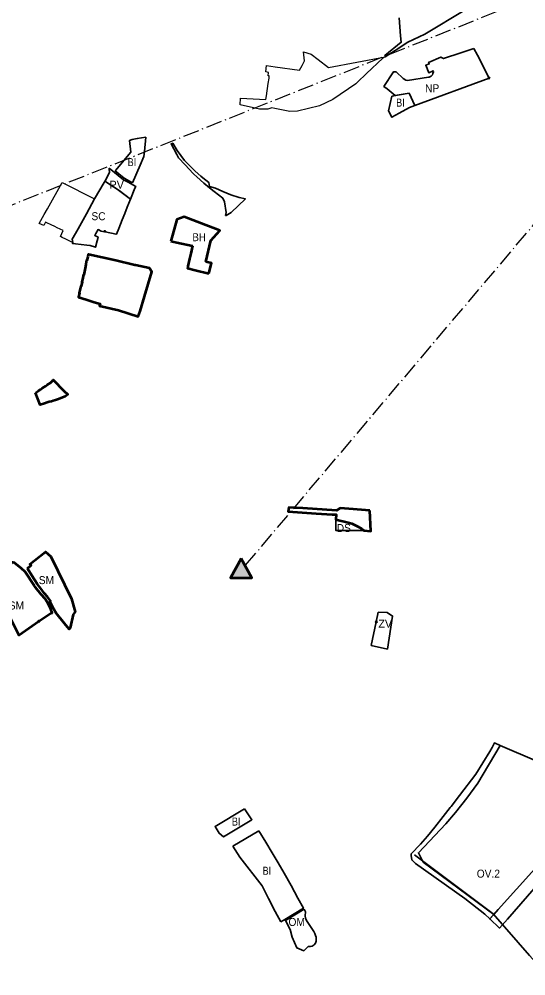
# Model space of a CAD drawing. Extents: x -650276 to -642489, y -1074311 to -1066658.
# Drawn here: x -646929 to -646170, y -1071706 to -1070271 of the extents above; entities that cross this region are included whole.
import ezdxf

# ---------------------------------------------------------------- set-up
doc = ezdxf.new("R2010")
doc.units = 0
doc.header["$LTSCALE"] = 4.8
doc.header["$PDMODE"] = 32
doc.header["$PDSIZE"] = 2.4
doc.linetypes.add('DOT_DASHED', pattern=[7.7, 5, -1.2, 0.3, -1.2])
for name, color, linetype, lineweight in [('1', 7, 'Continuous', 35), ('11', 7, 'Continuous', 35), ('12', 7, 'Continuous', 35), ('15', 7, 'Continuous', 35), ('17', 7, 'Continuous', 35), ('18', 7, 'Continuous', 35), ('2', 7, 'Continuous', 35), ('24', 7, 'Continuous', 35), ('40', 7, 'Continuous', 35), ('48', 7, 'Continuous', 35), ('54', 7, 'Continuous', 35), ('55', 7, 'Continuous', 53), ('60', 7, 'Continuous', 53), ('61', 7, 'Continuous', 25)]:
    doc.layers.add(name, color=color, linetype=linetype, lineweight=lineweight)
doc.layers.add('62', color=7, linetype='Continuous')
doc.layers.add('63', color=7, linetype='Continuous')

msp = doc.modelspace()

# ---------------------------------------------------------------- hatches: boundary and pattern name
at = {"layer": '55'}
msp.add_hatch(color=256, dxfattribs=at).paths.add_polyline_path([(-646596.857, -1071079.969), (-646612.808, -1071108.615), (-646580.424, -1071108.615)])

# ---------------------------------------------------------------- linework, layer by layer
at = {"layer": '1'}
msp.add_line((-646665.42, -1070647.54), (-646645.03, -1070652.34), dxfattribs=at)
for points in [[(-646655.95, -1070577.64), (-646682.29, -1070567.36), (-646692.98, -1070571.45), (-646701.87, -1070603.92)], [(-646649.71, -1070634.85), (-646642.32, -1070603.3), (-646628.69, -1070588.27), (-646655.95, -1070577.64)], [(-646701.87, -1070603.92), (-646693.18, -1070605.83), (-646669.59, -1070611.01), (-646672.13, -1070622.41), (-646673.91, -1070630.38), (-646676.414, -1070641.58)], [(-646676.414, -1070641.58), (-646676.81, -1070643.36), (-646677.13, -1070644.78), (-646665.42, -1070647.54)], [(-646645.03, -1070652.34), (-646641.09, -1070636.89), (-646649.71, -1070634.85)]]:
    msp.add_lwpolyline(points, dxfattribs=at)
at = {"layer": '11'}
msp.add_lwpolyline([(-646066.165, -1071422.155), (-646153.5, -1071383.85), (-646208.577, -1071360.044), (-646241.68, -1071416.887), (-646258.487, -1071439.265), (-646275.615, -1071460.886), (-646289.976, -1071477.514), (-646330.914, -1071521.11), (-646324, -1071535), (-646217.978, -1071613.552), (-646211.407, -1071606.247), (-646156.471, -1071545.166), (-646094.063, -1071471.007)], close=True, dxfattribs=at)
at = {"layer": '12'}
msp.add_lwpolyline([(-646502.39, -1071605.72), (-646530.27, -1071622.79), (-646522.99, -1071636.22), (-646520.32, -1071647.59), (-646513.43, -1071663.64), (-646502.53, -1071667.82), (-646496.06, -1071661.5), (-646492.89, -1071661.75), (-646490.07, -1071660.88), (-646487.36, -1071659.1), (-646485.29, -1071656.53), (-646484.15, -1071653.38), (-646483.97, -1071650.63), (-646484.38, -1071647.41), (-646485.2, -1071644.85), (-646486.31, -1071641.97), (-646487.56, -1071639.23), (-646497.83, -1071624.02), (-646499.829, -1071620.704), (-646500.289, -1071619.291), (-646500.83, -1071615.62), (-646500.34, -1071609.66)], close=True, dxfattribs=at)
at = {"layer": '15'}
for points in [[(-646623.95, -1070529.36), (-646634.85, -1070524.43), (-646644.2, -1070522.08), (-646645.31, -1070515.85), (-646654, -1070509), (-646656.83, -1070506.66), (-646665.457, -1070499.019), (-646667.42, -1070497.28), (-646681.6, -1070482.89), (-646692.74, -1070468.28), (-646699.26, -1070457.2), (-646701.65, -1070457.93), (-646693.119, -1070474.009), (-646690.316, -1070479.212), (-646680.44, -1070489.669), (-646668.361, -1070502.459), (-646667.369, -1070503.36), (-646662.895, -1070507.428), (-646652.352, -1070517.013), (-646643.895, -1070524.284), (-646637.158, -1070529.564), (-646624.211, -1070539.711), (-646621.729, -1070545.248), (-646619.34, -1070560.95), (-646619.99, -1070565.54), (-646619.15, -1070565.53), (-646611.41, -1070560.96), (-646590.2, -1070540.66), (-646599.81, -1070538.51), (-646611.88, -1070534.82)], [(-646275.615, -1071460.886), (-646258.487, -1071439.265), (-646241.68, -1071416.887), (-646208.577, -1071360.044), (-646217.049, -1071356.382), (-646220.61, -1071363.16), (-646223.77, -1071369.24), (-646245.1, -1071403.04), (-646269.2, -1071435.22), (-646281.99, -1071451.4), (-646283.52, -1071453.34), (-646293.87, -1071466.43), (-646306.14, -1071482.86), (-646317.52, -1071496.12), (-646327.97, -1071508.29), (-646341.88, -1071522.81), (-646341.66, -1071524.87), (-646340.93, -1071531.64), (-646335.3, -1071537.05), (-646261.46, -1071589.38), (-646231.43, -1071613.06), (-646223.928, -1071620.168), (-646217.978, -1071613.552), (-646324, -1071535), (-646330.914, -1071521.11), (-646289.976, -1071477.514), (-646275.615, -1071460.886)]]:
    msp.add_lwpolyline(points, close=True, dxfattribs=at)
for points in [[(-646794.59, -1070494.62), (-646794.53, -1070495.7), (-646793.75, -1070501.26), (-646800.6, -1070513.43), (-646800.94, -1070514.04)], [(-646755.84, -1070524.5), (-646754.52, -1070522.08), (-646765.96, -1070515.75), (-646770.95, -1070512.94), (-646773, -1070511.96), (-646794.59, -1070494.62)], [(-646800.94, -1070514.04), (-646788, -1070522.49), (-646782.63, -1070526.02)], [(-646782.63, -1070526.02), (-646779.68, -1070527.87), (-646762.71, -1070540.85), (-646755.84, -1070524.5)], [(-646156.471, -1071545.166), (-646211.407, -1071606.247), (-646223.928, -1071620.168), (-646209.322, -1071634.004), (-646197.398, -1071620.579), (-646077.593, -1071482.499)]]:
    msp.add_lwpolyline(points, dxfattribs=at)
at = {"layer": '17'}
msp.add_lwpolyline([(-646802.19, -1070516.26), (-646816.42, -1070540.49), (-646828.45, -1070562.89), (-646841.16, -1070585.79), (-646844.76, -1070592.54), (-646849.72, -1070600.98), (-646848.99, -1070606.28), (-646849.59, -1070607.4), (-646844.96, -1070607.98), (-646827.88, -1070610.12), (-646822.99, -1070610.51), (-646815.05, -1070613.14), (-646812.5, -1070603.78), (-646811.5, -1070600.29), (-646810.82, -1070598.23), (-646816.11, -1070595.8), (-646814.52, -1070592.78), (-646811.06, -1070586.67), (-646806.41, -1070589), (-646802.06, -1070589.93), (-646801.73, -1070588.37), (-646800.13, -1070588.71), (-646800.47, -1070590.28), (-646784.18, -1070593.76), (-646784, -1070593.34), (-646783.59, -1070593.52), (-646779.9, -1070584.92), (-646774.91, -1070571.88), (-646771.17, -1070562.7), (-646767.63, -1070553.09), (-646762.71, -1070540.85), (-646782.63, -1070526.02), (-646788, -1070522.49), (-646800.94, -1070514.04)], close=True, dxfattribs=at)
at = {"layer": '18'}
for points in [[(-646881.89, -1071077.03), (-646890.12, -1071069.67), (-646913.49, -1071088.22), (-646911.58, -1071089.9), (-646917.04, -1071094.75), (-646910.53, -1071105.18), (-646902.62, -1071117.58), (-646895.56, -1071126.84), (-646892.339, -1071131.481), (-646886.78, -1071137.25), (-646882.37, -1071143.39), (-646883.63, -1071144.15), (-646873.89, -1071161.58), (-646861.58, -1071177.05), (-646854.49, -1071185.87), (-646852.86, -1071183.98), (-646848.58, -1071163.95), (-646845.39, -1071159.98), (-646850.93, -1071140.54)], [(-646951.831, -1071107.765), (-646955.138, -1071114.466), (-646962.471, -1071129.325), (-646955.2, -1071143.67), (-646929.64, -1071194.58), (-646899.85, -1071173.89), (-646881.68, -1071161.83), (-646879.91, -1071161.24), (-646881.97, -1071155.84), (-646887.07, -1071145.66), (-646890.59, -1071140.39), (-646896.62, -1071133.93), (-646904.64, -1071123.54), (-646906.72, -1071120.46), (-646920.54, -1071099.98), (-646925.88, -1071094.68), (-646936.51, -1071086.33), (-646940.67, -1071085.15), (-646940.67, -1071085.15)]]:
    msp.add_lwpolyline(points, close=True, dxfattribs=at)
msp.add_point((-646899.85, -1071173.89), dxfattribs=at)
at = {"layer": '2'}
msp.add_line((-646609.21, -1071510.98), (-646570, -1071488.38), dxfattribs=at)
for points in [[(-646344.93, -1070382.33), (-646336.25, -1070400.875), (-646344.26, -1070403.84), (-646359.769, -1070412.361), (-646370.56, -1070418.29), (-646375.63, -1070408.76), (-646370.624, -1070386.792)], [(-646591.65, -1071454.91), (-646635.79, -1071481.6), (-646629.37, -1071491.74), (-646623.18, -1071496.99), (-646580.58, -1071471.48)]]:
    msp.add_lwpolyline(points, close=True, dxfattribs=at)
for points in [[(-646739.74, -1070447.98), (-646752.29, -1070450.28), (-646760.03, -1070451.56), (-646763.94, -1070452.95), (-646761.8, -1070470.4), (-646785.15, -1070498.05), (-646785.5, -1070498.47)], [(-646759.42, -1070516.37), (-646747.89, -1070489.87), (-646742.37, -1070477.2), (-646741.33, -1070469.79), (-646739.74, -1070447.98)], [(-646785.5, -1070498.47), (-646771.9, -1070509.4), (-646759.42, -1070516.37)], [(-646570, -1071488.38), (-646559.53, -1071505.12), (-646550.23, -1071520.88), (-646541.14, -1071536.3), (-646532.04, -1071551.72), (-646521.8, -1071570.34), (-646511.47, -1071589.11), (-646503.31, -1071603.95), (-646531.2, -1071621.07), (-646537.28, -1071624.8)], [(-646537.28, -1071624.8), (-646545.89, -1071609.07), (-646555.78, -1071589.66), (-646565.17, -1071570.4), (-646598.63, -1071527.8), (-646609.21, -1071510.98)]]:
    msp.add_lwpolyline(points, dxfattribs=at)
at = {"layer": '24'}
msp.add_lwpolyline([(-646454.59, -1071021.54), (-646454.59, -1071038), (-646412.54, -1071038.01), (-646415.61, -1071035.4), (-646421.58, -1071031.81), (-646430.91, -1071027.44)], close=True, dxfattribs=at)
at = {"layer": '40'}
for points in [[(-646377.5, -1071215.56), (-646369.76, -1071166.06), (-646377.87, -1071160.66), (-646391.07, -1071160.52), (-646394.05, -1071174.83)], [(-646394.05, -1071174.83), (-646401.64, -1071210.18), (-646377.5, -1071215.56)]]:
    msp.add_lwpolyline(points, dxfattribs=at)
msp.add_point((-646394.05, -1071174.83), dxfattribs=at)
at = {"layer": '48'}
msp.add_lwpolyline([(-646359.89, -1070269.01), (-646357.73, -1070296.13), (-646356.8, -1070305.73), (-646381.25, -1070325.85), (-646380.69, -1070327.47), (-646365.63, -1070318.37), (-646346.57, -1070305.88), (-646321.24, -1070293.85), (-646259.91, -1070256.89)], dxfattribs=at)
msp.add_lwpolyline([(-646247.667, -1070315.004), (-646267.3, -1070321.61), (-646293.14, -1070330.3), (-646297.4, -1070328.01), (-646315.84, -1070336.13), (-646314.84, -1070338.41), (-646319.95, -1070340.42), (-646315.46, -1070351.67), (-646308.791, -1070348.855), (-646308.59, -1070350.22), (-646309.18, -1070352.77), (-646309.99, -1070354.58), (-646311.82, -1070356.89), (-646314.6, -1070358.05), (-646315.7, -1070358.27), (-646347.49, -1070363.01), (-646349.76, -1070362.69), (-646353.81, -1070360.18), (-646364.34, -1070350.19), (-646368.4, -1070350.41), (-646382.67, -1070371.94), (-646377.86, -1070375.71), (-646365.7, -1070385.89), (-646344.93, -1070382.33), (-646336.35, -1070400.9), (-646225.15, -1070359.46), (-646242.56, -1070325.1)], close=True, dxfattribs=at)
msp.add_point((-646225.15, -1070359.46), dxfattribs=at)
at = {"layer": '54'}
msp.add_lwpolyline([(-646336.784, -1071524.232), (-646218.737, -1071612.767), (-646164.374, -1071674.897), (-645904.456, -1071961.331), (-645718.199, -1072151.712), (-645526.944, -1072343.922), (-645538, -1072384), (-645459, -1072440), (-645389, -1072483), (-645335, -1072526), (-645287, -1072569), (-645227, -1072617), (-645139.573, -1072694.628), (-645084.365, -1072788.086)], dxfattribs=at)
at = {"layer": '55', "linetype": 'DOT_DASHED', "lineweight": 25}
for p, q in [((-647060.176, -1070597.455), (-645765.418, -1070080.935)), ((-646590, -1071090), (-645744.292, -1070089.84))]:
    msp.add_line(p, q, dxfattribs=at)
at = {"layer": '55'}
msp.add_lwpolyline([(-646596.857, -1071079.969), (-646612.808, -1071108.615), (-646580.424, -1071108.615)], close=True, dxfattribs=at)
at = {"layer": '60'}
for points in [[(-646655.95, -1070577.64), (-646682.29, -1070567.36), (-646692.98, -1070571.45), (-646701.87, -1070603.92)], [(-646649.71, -1070634.85), (-646642.32, -1070603.3), (-646628.69, -1070588.27), (-646655.95, -1070577.64)], [(-646701.87, -1070603.92), (-646693.18, -1070605.83), (-646669.59, -1070611.01)], [(-646669.59, -1070611.01), (-646672.13, -1070622.41), (-646673.91, -1070630.38), (-646676.414, -1070641.58)], [(-646676.414, -1070641.58), (-646676.81, -1070643.36), (-646677.13, -1070644.78), (-646665.42, -1070647.54), (-646645.03, -1070652.34)], [(-646645.03, -1070652.34), (-646641.09, -1070636.89), (-646649.71, -1070634.85)]]:
    msp.add_lwpolyline(points, dxfattribs=at)
for points in [[(-646825.54, -1070624.03), (-646826.12, -1070623.9), (-646826.45, -1070627.3), (-646827.98, -1070632.83), (-646828.22, -1070632.77), (-646829.55, -1070638.78), (-646829.55, -1070638.78), (-646829.3, -1070638.83), (-646830.51, -1070644.3), (-646830.26, -1070644.35), (-646832.46, -1070654.31), (-646832.7, -1070654.26), (-646834.27, -1070661.39), (-646834.27, -1070661.39), (-646834.4, -1070661.35), (-646835.23, -1070665.08), (-646835.1, -1070665.12), (-646836.6, -1070671.54), (-646836.6, -1070671.54), (-646836.87, -1070671.46), (-646839.27, -1070681.62), (-646838.96, -1070681.72), (-646840.36, -1070687.86), (-646828.7, -1070691.73), (-646816.84, -1070695.43), (-646808.09, -1070698.19), (-646808.76, -1070701.11), (-646780.44, -1070707.59), (-646751.23, -1070717), (-646748.04, -1070709.23), (-646741.52, -1070687.22), (-646730.66, -1070650.07), (-646734.18, -1070644.6), (-646755.21, -1070639.87), (-646755.84, -1070639.88), (-646784.62, -1070633.19)], [(-646904.8, -1070831.23), (-646900.57, -1070828.42), (-646900.09, -1070828.1), (-646897.34, -1070826.28), (-646894.84, -1070824.62), (-646892.34, -1070822.96), (-646889.85, -1070821.3), (-646887.3, -1070819.61), (-646884.68, -1070817.87), (-646882.18, -1070816.21), (-646878.66, -1070812.72), (-646878.61, -1070812.14), (-646862.56, -1070828.29), (-646856.41, -1070834.13), (-646860.55, -1070836.71), (-646871.78, -1070841.33), (-646875.05, -1070842.32), (-646878.26, -1070843.29), (-646881.11, -1070844.21), (-646884.27, -1070845.17), (-646887.32, -1070846.14), (-646891.42, -1070847.44), (-646897.71, -1070849.39), (-646901.26, -1070840.31)], [(-646403.81, -1071007.7), (-646435.28, -1071005.2), (-646448.48, -1071004.25), (-646453.7, -1071007.79), (-646504.25, -1071004.54), (-646516.78, -1071003.78), (-646525.4, -1071003.29), (-646526.31, -1071009.55), (-646484.27, -1071012.11), (-646460.09, -1071013.61), (-646454.02, -1071013.98), (-646454.59, -1071021.54), (-646436.15, -1071025.97), (-646430.91, -1071027.44), (-646421.58, -1071031.81), (-646415.61, -1071035.4), (-646412.54, -1071038.01), (-646402.09, -1071038.95)], [(-646917.04, -1071094.75), (-646911.58, -1071089.9), (-646913.49, -1071088.22), (-646906.17, -1071082.72), (-646890.12, -1071069.67), (-646881.89, -1071077.03), (-646850.93, -1071140.54), (-646845.39, -1071159.98), (-646848.58, -1071163.95), (-646852.86, -1071183.98), (-646854.49, -1071185.87), (-646861.58, -1071177.05), (-646873.89, -1071161.58), (-646877.226, -1071155.611), (-646883.63, -1071144.15), (-646882.37, -1071143.39), (-646886.78, -1071137.25), (-646892.11, -1071131.81), (-646895.56, -1071126.84), (-646902.62, -1071117.58), (-646910.53, -1071105.18)], [(-646951.831, -1071107.765), (-646955.138, -1071114.466), (-646962.471, -1071129.325), (-646955.2, -1071143.67), (-646929.64, -1071194.58), (-646899.85, -1071173.89), (-646881.68, -1071161.83), (-646879.91, -1071161.24), (-646881.97, -1071155.84), (-646887.07, -1071145.66), (-646890.59, -1071140.39), (-646896.62, -1071133.93), (-646904.64, -1071123.54), (-646906.72, -1071120.46), (-646920.54, -1071099.98), (-646925.88, -1071094.68), (-646936.51, -1071086.33), (-646940.67, -1071085.15)]]:
    msp.add_lwpolyline(points, close=True, dxfattribs=at)
at = {"layer": '61'}
for points in [[(-646503.36, -1070320.39), (-646491.81, -1070323.54), (-646481.1, -1070331.76), (-646465.85, -1070343.46), (-646380.69, -1070327.47), (-646384.18, -1070329.58), (-646408.97, -1070352.57), (-646422.07, -1070365.6), (-646424.74, -1070368.25), (-646459.18, -1070391.48), (-646479.26, -1070401.17), (-646512.38, -1070409.18), (-646523.89, -1070409.54), (-646541.25, -1070406.02), (-646545.97, -1070405.06), (-646550.91, -1070404.27), (-646556.66, -1070406.07), (-646569.39, -1070406.06), (-646598.16, -1070399.848), (-646597.44, -1070389.891), (-646559.41, -1070391.82), (-646558.74, -1070386.15), (-646556, -1070367.59), (-646554.86, -1070359.63), (-646554.86, -1070359.63), (-646554.42, -1070356.22), (-646556.1, -1070356), (-646555.42, -1070350.94), (-646559.71, -1070350.35), (-646558.49, -1070340.9), (-646545.77, -1070342.7), (-646509.08, -1070347.79), (-646505.44, -1070340.51), (-646501.94, -1070333.51)], [(-646867.54, -1070597.11), (-646863.26, -1070588.3), (-646872.19, -1070583.97), (-646876.02, -1070582.12), (-646877.88, -1070581.22), (-646879.541, -1070580.417), (-646889.9, -1070575.41), (-646892.4, -1070580.64), (-646899.2, -1070577.61), (-646891.65, -1070564.15), (-646886.72, -1070555.37), (-646864.73, -1070516.2), (-646816.66, -1070540.37), (-646816.42, -1070540.49), (-646828.45, -1070562.89), (-646838.95, -1070581.53), (-646841.16, -1070585.79), (-646844.76, -1070592.54), (-646849.72, -1070600.98), (-646849.72, -1070600.98), (-646848.99, -1070606.28), (-646852.3, -1070604.63), (-646859.48, -1070601.1), (-646865.02, -1070598.34)]]:
    msp.add_lwpolyline(points, close=True, dxfattribs=at)

# ---------------------------------------------------------------- texts
at = {"layer": '62'}
for s, width, p in [('NP', 0.95, (-646320.99, -1070380.819)), ('BI', 0.85, (-646364.337, -1070402.32)), ('BI', 0.85, (-646766.828, -1070491.569)), ('SC', 0.95, (-646821.06, -1070572.645)), ('DS', 0.95, (-646453.386, -1071040.148)), ('SM', 0.95, (-646899.938, -1071118.245)), ('SM', 0.95, (-646944.938, -1071156.245)), ('BI', 0.85, (-646610.515, -1071480.22)), ('BI', 0.85, (-646564.529, -1071553.971)), ('OV.2', 0.95, (-646243.486, -1071558.306)), ('OM', 0.95, (-646525.703, -1071630.756))]:
    msp.add_text(s, height=12, dxfattribs=dict(at, width=width)).set_placement(p)
for s, p in [('PV', (-646793.831, -1070525.433)), ('ZV', (-646390.931, -1071183.591))]:
    msp.add_text(s, height=12, dxfattribs=at).set_placement(p)
at = {"layer": '63', "width": 0.9}
msp.add_text('BH', height=12, dxfattribs=at).set_placement((-646669.646, -1070604.101))

doc.saveas('drawing.dxf')
